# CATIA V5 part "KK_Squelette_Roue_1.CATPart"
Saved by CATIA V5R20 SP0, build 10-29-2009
Part number: Squelette_roue_1
Bounding box of the stored display mesh (mm): x 280 to 680, y 1056 to 1056, z -3072 to -2400
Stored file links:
  G:\Khaled_CFAO_2011\ST2M\ST2M_GR2\aboulegue\Khaled\CAD_thinkMOTION\KK_Squelette_Roue_1.CATPart
  G:\Khaled_CFAO_2011\ST2M\ST2M_GR2\aboulegue\Khaled\CAD_thinkMOTION\KK_Train_Atterrissage.CATProduct
  G:\Khaled_CFAO_2011\ST2M\ST2M_GR2\aboulegue\CFAO_aboulegue\CFAO_aboulegue_fichiers_catia\Squelette_general.CATPart
  G:\Khaled_CFAO_2011\ST2M\ST2M_GR2\aboulegue\CFAO_aboulegue\CFAO_aboulegue_fichiers_catia\Squelette_tige_amortisseur.CATPart
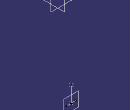
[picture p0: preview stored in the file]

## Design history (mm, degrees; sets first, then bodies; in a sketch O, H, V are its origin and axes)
Set1
  Plane1 "Plan reference": linked copy from another document
  Point1: linked copy from another document
  Point2: linked copy from another document
Set2 "Set_squelette_roue_1"
  Line1: type Normal, RefPoint Point1, RefSkin Plane1, Start -200, End 200
  Line2: type PtPt, FirstPoint Point1, SecondPoint Point2
  Plane2 "Plan roue 1": type 2Lines, Element1 Line1, Element2 Line2
Body1 (main body)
